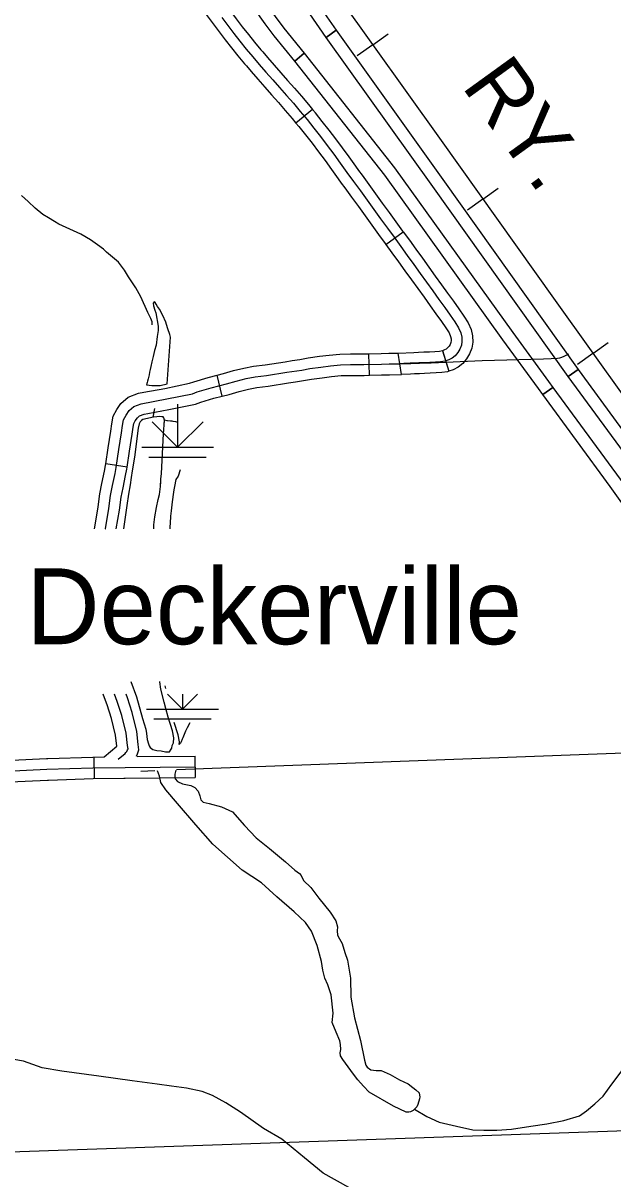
# Model space of a CAD drawing. Extents: x -117616 to 64730, y 54117 to 789866.
# Drawn here: x 62663.9 to 62746.1, y 54994.3 to 55155.2 of the extents above; entities that cross this region are included whole.
import ezdxf

# ---------------------------------------------------------------- set-up
doc = ezdxf.new("R2010")
doc.units = 0
for name, color, linetype in [('2', 7, 'Continuous'), ('35', 7, 'Continuous'), ('6', 7, 'Continuous'), ('Level 19', 7, 'Continuous'), ('Level 25', 7, 'Continuous'), ('Level 31', 7, 'Continuous'), ('Level 35', 7, 'Continuous'), ('Level 40', 7, 'Continuous'), ('Level 44', 7, 'Continuous'), ('Level 45', 7, 'Continuous'), ('Level 47', 7, 'Continuous')]:
    doc.layers.add(name, color=color, linetype=linetype)

msp = doc.modelspace()

# ---------------------------------------------------------------- linework, layer by layer
at = {"layer": '2'}
for points in [[(62771.13, 55054.4), (62770.93, 55054.39), (62767.59, 55054.28), (62685.31, 55051.22)], [(62682.28, 55051.08), (62680.31, 55051.01)]]:
    msp.add_lwpolyline(points, dxfattribs=at)
at = {"layer": '35'}
for points in [[(62717.55, 55007.51), (62718.22, 55007.02), (62718.63, 55006.67), (62719.12, 55006.25), (62719.14, 55005.96), (62719.18, 55005.72), (62719.16, 55005.43), (62718.94, 55004.64), (62718.79, 55004.31), (62718.44, 55003.98), (62718.26, 55003.83), (62717.91, 55003.61), (62717.67, 55003.59), (62717.29, 55003.59), (62715.51, 55004.4), (62712.14, 55006.38), (62711.37, 55007.22), (62710.54, 55008.1), (62709.94, 55008.89), (62708.47, 55010.9), (62708.14, 55011.42), (62708.1, 55011.86), (62708.18, 55012.3), (62708.14, 55013.01), (62708.07, 55013.52), (62707.52, 55014.73), (62706.97, 55016.07), (62707.13, 55017.37), (62706.86, 55019.92), (62706.38, 55021.31), (62705.96, 55022.21), (62705.7, 55023.33), (62705.52, 55024.55), (62704.88, 55026.79), (62704.12, 55028.75), (62703.28, 55029.98), (62701.7, 55031.48), (62699.28, 55033.57), (62697.16, 55035.49), (62694.44, 55037.25), (62690.34, 55040.86), (62688.01, 55043.59), (62685.42, 55046.52), (62683.79, 55048.43), (62683.13, 55049.47), (62682.93, 55050.33), (62682.64, 55051.1)], [(62685.2, 55051.19), (62685.07, 55050.64), (62685.07, 55050.24), (62685.11, 55049.98), (62685.42, 55049.6), (62686.15, 55049.27), (62687.31, 55049.03), (62687.83, 55048.75), (62688.3, 55048.25), (62688.56, 55047.59), (62688.7, 55047.07), (62689.03, 55046.74), (62689.84, 55046.55), (62691.56, 55046.08), (62693.1, 55045.37), (62694.75, 55043.48), (62696.38, 55041.77), (62698.27, 55040.29), (62700.47, 55038.44), (62701.79, 55037.24), (62702.43, 55036.79), (62702.66, 55036.53), (62702.99, 55035.82), (62703.99, 55034.85), (62705.12, 55033.36), (62706.7, 55031.4), (62707.48, 55030.19), (62707.74, 55029.39), (62707.67, 55028.82), (62707.74, 55028.23), (62708, 55027.71), (62708.4, 55027.05), (62708.76, 55025.82), (62709.11, 55024.73), (62709.54, 55022.22), (62709.58, 55019.58), (62710.1, 55016.69), (62710.91, 55013.57), (62711.5, 55010.83), (62711.69, 55010.1), (62711.85, 55009.84), (62712.35, 55009.48), (62713.1, 55009.39), (62713.81, 55009.36), (62715.06, 55008.8), (62716.36, 55008.09), (62717.55, 55007.51)], [(62718.44, 55003.98), (62720.18, 55003), (62721.9, 55002.19), (62724.3, 55001.63), (62726.58, 55001.13), (62728.11, 55001.07), (62729.92, 55001.07), (62731.98, 55001.22), (62734.67, 55001.63), (62736.88, 55001.97), (62739.25, 55002.41), (62741.44, 55003.07), (62742.41, 55003.75), (62743.56, 55004.72), (62744.72, 55005.81), (62745.97, 55007.47), (62747.25, 55009.19), (62749.12, 55012.03), (62750.88, 55014.29)], [(62709.3, 54993.11), (62705.73, 54995.11), (62703.15, 54997.24), (62699.96, 54999.82), (62697.44, 55001.31), (62694.19, 55003.57), (62692.16, 55004.86), (62690.29, 55005.92), (62688.87, 55006.47), (62686.68, 55006.92), (62684.62, 55007.21), (62682.62, 55007.47), (62679.14, 55007.92), (62674.46, 55008.57), (62669.34, 55009.31), (62666.57, 55009.76), (62663.96, 55010.69), (62661.57, 55011.11), (62660.44, 55011.19)]]:
    msp.add_lwpolyline(points, dxfattribs=at)
at = {"layer": '6'}
msp.add_lwpolyline([(62765.46, 55001.58), (62660.76, 54997.96)], dxfattribs=at)
at = {"layer": 'Level 19'}
msp.add_line((62743.32, 55109.18), (62741.17, 55107.64), dxfattribs=at)
for points in [[(62689.41, 55179.53), (62691.19, 55177.06), (62705.25, 55157.42), (62707.56, 55154.15)], [(62706.17, 55153.17), (62703.86, 55156.43), (62689.81, 55176.07), (62688.03, 55178.54)], [(62685.88, 55177.02), (62692, 55166.87), (62697.59, 55158.07), (62699.02, 55156.07), (62700.26, 55154.45), (62703.1, 55150.95)], [(62701.78, 55149.88), (62698.92, 55153.4), (62697.66, 55155.06), (62696.18, 55157.12), (62690.55, 55165.97), (62684.5, 55176.03)], [(62707.56, 55154.15), (62706.17, 55153.17)], [(62706.17, 55153.17), (62707.56, 55154.15)], [(62707.56, 55154.15), (62722.39, 55133.41), (62741.26, 55106.96)], [(62739.87, 55105.97), (62721.01, 55132.42), (62706.17, 55153.17)], [(62703.1, 55150.95), (62701.78, 55149.88)], [(62701.78, 55149.88), (62703.1, 55150.95)], [(62703.1, 55150.95), (62715.66, 55134.99), (62732.16, 55112.09), (62737.12, 55105.29), (62737.72, 55104.46)], [(62736.33, 55103.47), (62735.74, 55104.3), (62730.78, 55111.09), (62714.3, 55133.97), (62701.78, 55149.88)], [(62741.26, 55106.96), (62739.87, 55105.97)], [(62739.87, 55105.97), (62741.26, 55106.96)], [(62741.26, 55106.96), (62750.61, 55094.19), (62759.94, 55081.15), (62769.42, 55068.06)], [(62768.05, 55067.07), (62758.56, 55080.16), (62749.23, 55093.2), (62739.87, 55105.97)], [(62737.72, 55104.46), (62736.33, 55103.47)], [(62736.33, 55103.47), (62737.72, 55104.46)], [(62737.72, 55104.46), (62747.09, 55091.67), (62756.41, 55078.64), (62765.93, 55065.53)], [(62764.56, 55064.54), (62755.03, 55077.64), (62745.71, 55090.68), (62736.33, 55103.47)]]:
    msp.add_lwpolyline(points, dxfattribs=at)
at = {"layer": 'Level 31'}
for p, q in [((62704.25, 55143.15), (62701.94, 55141.24)), ((62708.26, 55132.9), (62708.26, 55132.9)), ((62714.46, 55124.36), (62716.89, 55126.11)), ((62722.34, 55109.56), (62723.23, 55106.69)), ((62722.37, 55109.57), (62723.23, 55106.69))]:
    msp.add_line(p, q, dxfattribs=at)
for points in [[(62690.94, 55159.41), (62691.19, 55159.07), (62691.99, 55157.95), (62692.8, 55156.83), (62693.63, 55155.74), (62694.46, 55154.65), (62695.31, 55153.57), (62696.18, 55152.5), (62697.06, 55151.43), (62697.31, 55151.14)], [(62688.51, 55157.65), (62688.75, 55157.32), (62689.56, 55156.19), (62690.39, 55155.05), (62691.24, 55153.92), (62692.09, 55152.81), (62692.96, 55151.7), (62693.85, 55150.6), (62694.76, 55149.5), (62695.03, 55149.19)], [(62691.6, 55155.94), (62692.43, 55154.83), (62693.28, 55153.73), (62694.14, 55152.64), (62695.02, 55151.55), (62695.91, 55150.47), (62696.83, 55149.39), (62697.76, 55148.32), (62698.7, 55147.24), (62699.66, 55146.17), (62700.62, 55145.09), (62701.58, 55143.99), (62702.54, 55142.86), (62703.49, 55141.72), (62704.43, 55140.55), (62705.37, 55139.36), (62706.29, 55138.14), (62707.2, 55136.9), (62708.12, 55135.64), (62709.04, 55134.38), (62709.97, 55133.1), (62710.91, 55131.81), (62711.85, 55130.51), (62712.8, 55129.21), (62713.74, 55127.92), (62714.68, 55126.63), (62715.6, 55125.34), (62716.53, 55124.06), (62717.44, 55122.79), (62718.34, 55121.54), (62719.23, 55120.3), (62720.12, 55119.08), (62720.99, 55117.87), (62721.85, 55116.68), (62722.66, 55115.56), (62723.43, 55114.51), (62724.09, 55113.56), (62724.6, 55112.74), (62724.91, 55112.04), (62725.05, 55111.43), (62725.07, 55110.86), (62724.98, 55110.31), (62724.78, 55109.79), (62724.49, 55109.3), (62724.12, 55108.86), (62723.7, 55108.52), (62723.24, 55108.27), (62722.71, 55108.1), (62722.09, 55108), (62721.38, 55107.96), (62720.59, 55107.93), (62719.81, 55107.89), (62719.06, 55107.86), (62718.4, 55107.83), (62717.83, 55107.81), (62717.36, 55107.78), (62716.97, 55107.76), (62716.67, 55107.75), (62716.46, 55107.74)], [(62697.31, 55151.14), (62697.96, 55150.37), (62698.89, 55149.31), (62699.83, 55148.24), (62700.78, 55147.17), (62701.75, 55146.08), (62702.72, 55144.97), (62703.69, 55143.83), (62704.25, 55143.15)], [(62695.03, 55149.19), (62695.69, 55148.42), (62696.63, 55147.33), (62697.58, 55146.25), (62698.54, 55145.17), (62699.5, 55144.1), (62700.45, 55143.01), (62701.39, 55141.9), (62701.94, 55141.24)], [(62710.69, 55134.66), (62710.26, 55135.26), (62709.33, 55136.53), (62708.41, 55137.79), (62707.49, 55139.04), (62706.56, 55140.27), (62705.61, 55141.48), (62704.65, 55142.67), (62704.25, 55143.15)], [(62701.94, 55141.24), (62702.33, 55140.77), (62703.26, 55139.62), (62704.18, 55138.44), (62705.08, 55137.25), (62705.99, 55136.01), (62706.91, 55134.76), (62707.83, 55133.5), (62708.26, 55132.9)], [(62716.89, 55126.11), (62716.82, 55126.21), (62715.89, 55127.5), (62714.96, 55128.8), (62714.01, 55130.1), (62713.07, 55131.4), (62712.12, 55132.69), (62711.19, 55133.98), (62710.69, 55134.66)], [(62708.26, 55132.9), (62708.76, 55132.22), (62709.7, 55130.92), (62710.64, 55129.63), (62711.59, 55128.33), (62712.53, 55127.04), (62713.46, 55125.75), (62714.39, 55124.46), (62714.46, 55124.36)], [(62716.89, 55126.11), (62717.74, 55124.94), (62718.66, 55123.67), (62719.56, 55122.42), (62720.45, 55121.18), (62721.33, 55119.95), (62722.21, 55118.74), (62723.06, 55117.56), (62723.07, 55117.55)], [(62714.46, 55124.36), (62715.31, 55123.18), (62716.23, 55121.91), (62717.13, 55120.67), (62718.02, 55119.43), (62718.9, 55118.2), (62719.78, 55116.99), (62720.63, 55115.8), (62720.64, 55115.79)], [(62723.07, 55117.55), (62723.88, 55116.44), (62724.65, 55115.38), (62725.35, 55114.39), (62725.93, 55113.44), (62726.34, 55112.52), (62726.55, 55111.62), (62726.57, 55110.76), (62726.43, 55109.92), (62726.14, 55109.13), (62725.71, 55108.42), (62725.18, 55107.79), (62724.55, 55107.27), (62723.83, 55106.88), (62723.23, 55106.69)], [(62720.64, 55115.79), (62721.45, 55114.68), (62722.21, 55113.63), (62722.84, 55112.73), (62723.27, 55112.04), (62723.48, 55111.56), (62723.56, 55111.23), (62723.57, 55110.96), (62723.52, 55110.7), (62723.43, 55110.44), (62723.27, 55110.18), (62723.06, 55109.94), (62722.86, 55109.77), (62722.65, 55109.66), (62722.34, 55109.56)], [(62716.19, 55109.24), (62718.34, 55109.33), (62719, 55109.36), (62719.74, 55109.39), (62720.53, 55109.42), (62721.3, 55109.46), (62721.93, 55109.5), (62722.37, 55109.57)], [(62723.23, 55106.69), (62723.05, 55106.64), (62722.26, 55106.51), (62721.46, 55106.46), (62720.66, 55106.43), (62719.87, 55106.39), (62719.13, 55106.36), (62718.47, 55106.33), (62717.9, 55106.31), (62716.65, 55106.25), (62716.19, 55109.24)]]:
    msp.add_lwpolyline(points, dxfattribs=at)
at = {"layer": 'Level 35'}
for points in [[(62681.9, 55113.15), (62681.92, 55113.57), (62681.73, 55114.03), (62681.32, 55114.87), (62680.33, 55117.05), (62679.63, 55118.3), (62678.62, 55119.85), (62678.04, 55120.78), (62677.21, 55121.86), (62675.53, 55123.27), (62675.11, 55123.67), (62674.3, 55124.29), (62673.3, 55124.99), (62671.99, 55125.76), (62668.9, 55127.17), (62668.28, 55127.56), (62667.46, 55128.06), (62666.66, 55128.51), (62665.61, 55129.38), (62664.64, 55130.31), (62663.72, 55131.18)], [(62684, 55104.97), (62684.47, 55111.44), (62684.37, 55111.82), (62684.11, 55112.61), (62683.88, 55113.22), (62683.79, 55113.52), (62683.4, 55114.44), (62682.91, 55115.36), (62682.67, 55115.71), (62682.48, 55116.02), (62682.32, 55116.27), (62682.2, 55116.37), (62682.05, 55116.16), (62682.07, 55115.82), (62682.26, 55115.21), (62682.4, 55114.83), (62682.73, 55112.98), (62682.72, 55112.36), (62682.58, 55111.54), (62682.45, 55110.35), (62682.21, 55109.57), (62682.04, 55108.77), (62681.87, 55108.02), (62681.72, 55107.34), (62681.62, 55106.96), (62681.52, 55106.59), (62681.48, 55106.21), (62681.34, 55105.65), (62681.26, 55105.33), (62681.23, 55105.12), (62681.13, 55104.8), (62681.85, 55104.71), (62683.01, 55104.73), (62684, 55104.97)], [(62682.25, 55101.5), (62681.98, 55100.32)], [(62683.49, 55097.97), (62683.62, 55099.84), (62683.58, 55100.1), (62683.52, 55100.24), (62683.43, 55100.36), (62683.27, 55100.37), (62682.97, 55100.39), (62682.57, 55100.35), (62682.11, 55100.33), (62680.61, 55099.97), (62680.4, 55099.84), (62680.23, 55099.65), (62680.1, 55099.38), (62679.95, 55098.79), (62679.46, 55094.75), (62679.13, 55092.85), (62678.98, 55091.91), (62678.83, 55090.9), (62678.62, 55089.61), (62678.38, 55088.03), (62678.12, 55086.08), (62677.92, 55084.75)], [(62682.15, 55085.31), (62682.28, 55086.44), (62682.49, 55087.73), (62682.73, 55088.85), (62682.92, 55089.56), (62683.06, 55090.64), (62683.13, 55091.66), (62683.19, 55092.47), (62683.49, 55097.97)], [(62682.13, 55084.75), (62682.15, 55085.31)], [(62678.95, 55063.5), (62679.74, 55061.4), (62680.56, 55058.35), (62681.01, 55056.89), (62681.12, 55056.27), (62681.23, 55055.43), (62681.38, 55054.84), (62681.51, 55054.58), (62681.64, 55054.35), (62682.01, 55054.05), (62682.55, 55053.94), (62683.14, 55053.85), (62683.75, 55053.73), (62684.33, 55053.74), (62684.54, 55054.09), (62684.65, 55054.23), (62684.71, 55054.59), (62684.87, 55054.98), (62684.91, 55055.7), (62684.72, 55056.66), (62684.15, 55058.57), (62683.83, 55059.74), (62683.6, 55060.64), (62683.13, 55062.46), (62682.96, 55063.47), (62682.96, 55063.5)]]:
    msp.add_lwpolyline(points, dxfattribs=at)
at = {"layer": 'Level 40'}
for p, q in [((62712.63, 55152.15), (62714.78, 55153.68)), ((62712.63, 55152.15), (62710.48, 55150.61)), ((62727.97, 55130.66), (62730.12, 55132.2)), ((62727.97, 55130.66), (62725.82, 55129.13)), ((62743.32, 55109.18), (62745.46, 55110.72))]:
    msp.add_line(p, q, dxfattribs=at)
msp.add_lwpolyline([(62694.17, 55177.97), (62721.93, 55139.13), (62738.03, 55116.55), (62752.86, 55095.87), (62766.06, 55078.11), (62783.13, 55054.78)], dxfattribs=at)
msp.add_lwpolyline([(62694.17, 55177.97), (62721.93, 55139.13), (62738.03, 55116.55), (62752.86, 55095.87), (62766.06, 55078.11), (62783.13, 55054.78)], dxfattribs=at)
at = {"layer": 'Level 44'}
for p, q in [((62685.45, 55102.12), (62685.45, 55096.12)), ((62685.45, 55096.12), (62681.92, 55099.66)), ((62685.45, 55096.12), (62688.99, 55099.66)), ((62680.45, 55096.12), (62690.45, 55096.12)), ((62681.45, 55094.76), (62689.45, 55094.76)), ((62686.13, 55059.67), (62684.05, 55061.75)), ((62686.13, 55061.75), (62686.13, 55059.67)), ((62686.13, 55059.67), (62688.22, 55061.75)), ((62681.13, 55059.67), (62691.13, 55059.67)), ((62682.13, 55058.31), (62690.13, 55058.31))]:
    msp.add_line(p, q, dxfattribs=at)
at = {"layer": 'Level 45'}
for p, q in [((62712.18, 55106.14), (62712.11, 55109.14)), ((62691.66, 55103.24), (62690.94, 55106.15)), ((62678.41, 55093.36), (62675.45, 55093.82)), ((62673.86, 55050), (62673.82, 55053)), ((62687.94, 55050.14), (62687.9, 55053.14))]:
    msp.add_line(p, q, dxfattribs=at)
for points in [[(62675.38, 55084.75), (62675.39, 55084.77), (62675.88, 55087.6), (62676.11, 55089.41), (62676.38, 55090.78), (62676.73, 55092.48), (62676.89, 55093.3), (62677.27, 55095.83), (62677.65, 55098.15), (62677.77, 55099.15), (62677.91, 55099.94), (62678.27, 55100.58), (62678.7, 55101.22), (62679.35, 55101.8), (62680.38, 55102.18), (62683.95, 55102.84), (62687.52, 55103.58), (62688.19, 55103.82), (62690.12, 55104.4), (62692.26, 55104.93), (62693.63, 55105.34), (62694.99, 55105.68), (62696.26, 55105.94), (62697.85, 55106.11), (62700.66, 55106.55), (62702.75, 55106.87), (62703.88, 55107.08), (62705.4, 55107.29), (62706.74, 55107.44), (62708.15, 55107.59), (62709.55, 55107.62), (62711.4, 55107.62), (62713.84, 55107.68), (62714.93, 55107.71), (62716.39, 55107.74), (62717.94, 55107.8), (62719.17, 55107.83), (62720.77, 55107.89), (62727.9, 55108.18), (62736.45, 55108.42), (62737.51, 55108.47), (62738.4, 55108.53), (62738.72, 55108.57), (62738.99, 55108.65), (62739.3, 55108.78), (62739.69, 55108.98), (62739.98, 55109.13)], [(62701.42, 55108.18), (62702.5, 55108.35), (62703.64, 55108.56), (62705.21, 55108.78), (62706.57, 55108.93), (62708.05, 55109.09), (62709.54, 55109.12), (62711.38, 55109.12), (62712.11, 55109.14)], [(62712.11, 55109.14), (62713.8, 55109.18), (62714.89, 55109.21), (62716.19, 55109.24)], [(62690.94, 55106.15), (62691.86, 55106.38), (62693.24, 55106.79), (62694.66, 55107.14), (62696.03, 55107.42), (62697.65, 55107.6), (62700.44, 55108.03), (62701.42, 55108.18)], [(62680.75, 55103.77), (62683.66, 55104.32), (62687.12, 55105.03), (62687.72, 55105.25), (62689.72, 55105.85), (62690.94, 55106.15)], [(62701.88, 55105.22), (62703, 55105.39), (62704.12, 55105.6), (62705.58, 55105.8), (62706.9, 55105.95), (62708.25, 55106.09), (62709.57, 55106.12), (62711.42, 55106.12), (62712.18, 55106.14)], [(62712.18, 55106.14), (62713.88, 55106.18), (62714.96, 55106.21), (62716.65, 55106.25)], [(62675.45, 55093.82), (62675.79, 55096.06), (62676.17, 55098.35), (62676.28, 55099.37), (62676.47, 55100.46), (62677, 55101.37), (62677.55, 55102.2), (62678.56, 55103.11), (62679.99, 55103.63), (62680.75, 55103.77)], [(62691.66, 55103.24), (62692.65, 55103.48), (62694.03, 55103.89), (62695.32, 55104.22), (62696.49, 55104.45), (62698.05, 55104.63), (62700.89, 55105.07), (62701.88, 55105.22)], [(62681.3, 55100.82), (62684.24, 55101.37), (62687.93, 55102.13), (62688.67, 55102.4), (62690.51, 55102.96), (62691.66, 55103.24)], [(62678.41, 55093.36), (62678.76, 55095.59), (62679.14, 55097.94), (62679.25, 55098.94), (62679.34, 55099.42), (62679.55, 55099.79), (62679.84, 55100.23), (62680.13, 55100.49), (62680.78, 55100.73), (62681.3, 55100.82)], [(62673.87, 55084.75), (62673.9, 55084.99), (62674.4, 55087.83), (62674.63, 55089.64), (62674.91, 55091.08), (62675.26, 55092.78), (62675.41, 55093.56), (62675.45, 55093.82)], [(62676.91, 55084.75), (62677.37, 55087.38), (62677.59, 55089.17), (62677.85, 55090.49), (62678.2, 55092.19), (62678.36, 55093.05), (62678.41, 55093.36)], [(62675.21, 55053.02), (62676.98, 55054.5), (62676.81, 55056.05), (62676.22, 55058.39), (62675.62, 55060.26), (62675.13, 55061.61), (62675.07, 55061.75)], [(62677.18, 55052.71), (62678.14, 55053.51), (62678.26, 55053.62), (62678.38, 55053.79), (62678.48, 55054.01), (62678.54, 55054.17), (62678.48, 55054.59), (62678.29, 55056.31), (62677.66, 55058.8), (62677.04, 55060.74), (62676.67, 55061.75)], [(62679.71, 55053.11), (62679.87, 55053.44), (62680.07, 55054), (62679.97, 55054.77), (62679.77, 55056.58), (62679.1, 55059.21), (62678.46, 55061.23), (62678.27, 55061.75)], [(62654.59, 55052.21), (62667.19, 55052.8), (62667.35, 55052.8)], [(62667.35, 55052.8), (62673.62, 55053), (62675.21, 55053.02)], [(62679.8, 55053.07), (62687.9, 55053.14)], [(62656.85, 55050.81), (62667.25, 55051.3), (62673.65, 55051.5), (62678.14, 55051.56), (62687.91, 55051.64)], [(62657.94, 55049.36), (62667.31, 55049.8), (62667.44, 55049.81)], [(62667.44, 55049.81), (62673.69, 55050), (62677.97, 55050.06)], [(62677.97, 55050.06), (62678.16, 55050.06), (62687.92, 55050.14)]]:
    msp.add_lwpolyline(points, dxfattribs=at)
at = {"layer": 'Level 47'}
for points in [[(62683.58, 55099.3), (62683.62, 55099.93)], [(62683.62, 55099.93), (62683.96, 55099.86), (62684.04, 55099.84), (62684.44, 55099.82), (62684.66, 55099.82), (62684.8, 55099.76), (62685.16, 55099.72), (62685.31, 55099.65), (62685.32, 55099.64)], [(62685.83, 55092.98), (62685.51, 55092.11), (62685.21, 55091.65), (62685, 55090.65), (62684.94, 55090.21), (62684.9, 55089.87), (62684.69, 55088.51), (62684.57, 55087.26), (62684.47, 55086.51), (62684.4, 55085.58), (62684.39, 55085.04), (62684.38, 55084.75)], [(62682.15, 55085.31), (62682.28, 55086.44), (62682.49, 55087.73), (62682.73, 55088.85), (62682.92, 55089.56), (62683.06, 55090.64), (62683.11, 55091.35)], [(62682.13, 55084.75), (62682.15, 55085.31)], [(62683.8, 55062.55), (62683.74, 55062.9), (62683.74, 55062.93)], [(62685.68, 55054.77), (62685.7, 55055.13), (62685.51, 55056.08), (62684.99, 55057.82)], [(62687.16, 55057.78), (62686.76, 55057.09), (62686.54, 55056.6), (62686.19, 55055.7)], [(62686.19, 55055.7), (62686.1, 55055.49), (62685.94, 55055.14), (62685.85, 55054.95), (62685.68, 55054.77)]]:
    msp.add_lwpolyline(points, dxfattribs=at)

# ---------------------------------------------------------------- texts
at = {"layer": 'Level 25'}
msp.add_text('Deckerville', height=10.56, dxfattribs=at).set_placement((62664.38, 55068.71))
at = {"layer": 'Level 40'}
msp.add_text('RY.', height=8.448, rotation=305.8246, dxfattribs=at).set_placement((62724.91, 55146.4))

doc.saveas('drawing.dxf')
